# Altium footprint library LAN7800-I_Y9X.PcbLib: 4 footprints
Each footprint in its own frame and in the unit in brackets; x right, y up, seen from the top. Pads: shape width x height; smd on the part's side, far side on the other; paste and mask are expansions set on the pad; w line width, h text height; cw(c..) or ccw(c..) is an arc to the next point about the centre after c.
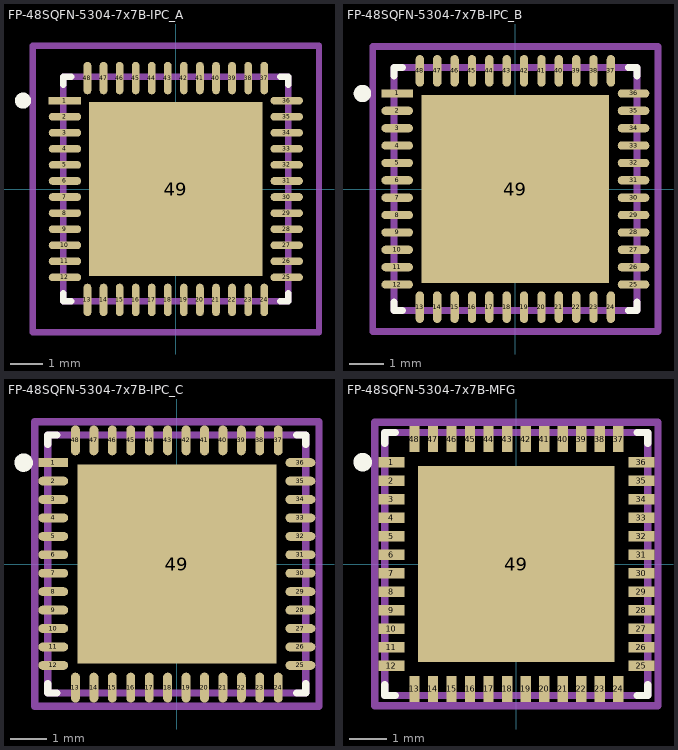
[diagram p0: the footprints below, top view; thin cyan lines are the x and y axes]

## FP-48SQFN-5304-7x7B-IPC_A [mm]
pads (49):
  rect 1.01x0.239 smd paste+0 mask+0: 1(-3.451,2.75)
  rrect100% 1.01x0.239 smd paste+0 mask+0: 2(-3.451,2.25) 3(-3.451,1.75) 4(-3.451,1.25) 5(-3.451,0.75) 6(-3.451,0.25) 7(-3.451,-0.25) 8(-3.451,-0.75) 9(-3.451,-1.25) 10(-3.451,-1.75) 11(-3.451,-2.25) 12(-3.451,-2.75) 25(3.451,-2.75) 26(3.451,-2.25) 27(3.451,-1.75) 28(3.451,-1.25) 29(3.451,-0.75) 30(3.451,-0.25) 31(3.451,0.25) 32(3.451,0.75) 33(3.451,1.25) 34(3.451,1.75) 35(3.451,2.25) 36(3.451,2.75)
  rrect100% 0.239x1.01 smd paste+0 mask+0: 13(-2.75,-3.451) 14(-2.25,-3.451) 15(-1.75,-3.451) 16(-1.25,-3.451) 17(-0.75,-3.451) 18(-0.25,-3.451) 19(0.25,-3.451) 20(0.75,-3.451) 21(1.25,-3.451) 22(1.75,-3.451) 23(2.25,-3.451) 24(2.75,-3.451) 37(2.75,3.451) 38(2.25,3.451) 39(1.75,3.451) 40(1.25,3.451) 41(0.75,3.451) 42(0.25,3.451) 43(-0.25,3.451) 44(-0.75,3.451) 45(-1.25,3.451) 46(-1.75,3.451) 47(-2.25,3.451) 48(-2.75,3.451)
  rect 5.4x5.4 smd paste-1000 mask+0: 49(0,0)
Top Overlay:
  circle w0.25: c-4.756,2.75 r0.125
  lines w0.2: -3.5,-3.25 -3.5,-3.5 -3.25,-3.5 ; -3.5,3.25 -3.5,3.5 -3.25,3.5 ; 3.25,-3.5 3.5,-3.5 3.5,-3.25 ; 3.25,3.5 3.5,3.5 3.5,3.25
Top Paste:
  rectangle: -2.038,0.331 -0.331,2.038
  rectangle: 0.331,0.331 2.038,2.038
  rectangle: -2.038,-2.038 -0.331,-0.331
  rectangle: 0.331,-2.038 2.038,-0.331
Top Assembly:
  lines w0.2: -4.456,-4.456 4.456,-4.456 4.456,4.456 -4.456,4.456 -4.456,-4.456
  text ".Designator" at 0,-0.001 h1
Top 3D Body:
  lines w0.2: -3.5,-3.5 3.5,-3.5 3.5,3.5 -3.5,3.5 -3.5,-3.5
Top Courtyard:
  lines w0.2: -4.456,-4.456 4.456,-4.456 4.456,4.456 -4.456,4.456 -4.456,-4.456
Top Component Center:
  lines w0.1: -0.5,0 0.5,0 ; 0,-0.5 0,0.5
3D body "IC_Microchip_LAN7800-I-Y9X_eec.STEP": height 0.25, standoff 0, extent -4.456,-4.456 4.456,4.456

## FP-48SQFN-5304-7x7B-IPC_B [mm]
pads (49):
  rect 0.91x0.239 smd paste+0 mask+0: 1(-3.401,2.75)
  rrect100% 0.91x0.239 smd paste+0 mask+0: 2(-3.401,2.25) 3(-3.401,1.75) 4(-3.401,1.25) 5(-3.401,0.75) 6(-3.401,0.25) 7(-3.401,-0.25) 8(-3.401,-0.75) 9(-3.401,-1.25) 10(-3.401,-1.75) 11(-3.401,-2.25) 12(-3.401,-2.75) 25(3.401,-2.75) 26(3.401,-2.25) 27(3.401,-1.75) 28(3.401,-1.25) 29(3.401,-0.75) 30(3.401,-0.25) 31(3.401,0.25) 32(3.401,0.75) 33(3.401,1.25) 34(3.401,1.75) 35(3.401,2.25) 36(3.401,2.75)
  rrect100% 0.239x0.91 smd paste+0 mask+0: 13(-2.75,-3.401) 14(-2.25,-3.401) 15(-1.75,-3.401) 16(-1.25,-3.401) 17(-0.75,-3.401) 18(-0.25,-3.401) 19(0.25,-3.401) 20(0.75,-3.401) 21(1.25,-3.401) 22(1.75,-3.401) 23(2.25,-3.401) 24(2.75,-3.401) 37(2.75,3.401) 38(2.25,3.401) 39(1.75,3.401) 40(1.25,3.401) 41(0.75,3.401) 42(0.25,3.401) 43(-0.25,3.401) 44(-0.75,3.401) 45(-1.25,3.401) 46(-1.75,3.401) 47(-2.25,3.401) 48(-2.75,3.401)
  rect 5.4x5.4 smd paste-1000 mask+0: 49(0,0)
Top Overlay:
  circle w0.25: c-4.406,2.75 r0.125
  lines w0.2: -3.5,-3.25 -3.5,-3.5 -3.25,-3.5 ; -3.5,3.25 -3.5,3.5 -3.25,3.5 ; 3.25,-3.5 3.5,-3.5 3.5,-3.25 ; 3.25,3.5 3.5,3.5 3.5,3.25
Top Paste:
  rectangle: -2.038,0.331 -0.331,2.038
  rectangle: 0.331,0.331 2.038,2.038
  rectangle: -2.038,-2.038 -0.331,-0.331
  rectangle: 0.331,-2.038 2.038,-0.331
Top Assembly:
  lines w0.2: -4.106,-4.106 4.106,-4.106 4.106,4.106 -4.106,4.106 -4.106,-4.106
  text ".Designator" at 0,-0.001 h1
Top 3D Body:
  lines w0.2: -3.5,-3.5 3.5,-3.5 3.5,3.5 -3.5,3.5 -3.5,-3.5
Top Courtyard:
  lines w0.2: -4.106,-4.106 4.106,-4.106 4.106,4.106 -4.106,4.106 -4.106,-4.106
Top Component Center:
  lines w0.1: -0.5,0 0.5,0 ; 0,-0.5 0,0.5
3D body "IC_Microchip_LAN7800-I-Y9X_eec.STEP": height 0.25, standoff 0, extent -4.106,-4.106 4.106,4.106

## FP-48SQFN-5304-7x7B-IPC_C [mm]
pads (49):
  rect 0.81x0.239 smd paste+0 mask+0: 1(-3.351,2.75)
  rrect100% 0.81x0.239 smd paste+0 mask+0: 2(-3.351,2.25) 3(-3.351,1.75) 4(-3.351,1.25) 5(-3.351,0.75) 6(-3.351,0.25) 7(-3.351,-0.25) 8(-3.351,-0.75) 9(-3.351,-1.25) 10(-3.351,-1.75) 11(-3.351,-2.25) 12(-3.351,-2.75) 25(3.351,-2.75) 26(3.351,-2.25) 27(3.351,-1.75) 28(3.351,-1.25) 29(3.351,-0.75) 30(3.351,-0.25) 31(3.351,0.25) 32(3.351,0.75) 33(3.351,1.25) 34(3.351,1.75) 35(3.351,2.25) 36(3.351,2.75)
  rrect100% 0.239x0.81 smd paste+0 mask+0: 13(-2.75,-3.351) 14(-2.25,-3.351) 15(-1.75,-3.351) 16(-1.25,-3.351) 17(-0.75,-3.351) 18(-0.25,-3.351) 19(0.25,-3.351) 20(0.75,-3.351) 21(1.25,-3.351) 22(1.75,-3.351) 23(2.25,-3.351) 24(2.75,-3.351) 37(2.75,3.351) 38(2.25,3.351) 39(1.75,3.351) 40(1.25,3.351) 41(0.75,3.351) 42(0.25,3.351) 43(-0.25,3.351) 44(-0.75,3.351) 45(-1.25,3.351) 46(-1.75,3.351) 47(-2.25,3.351) 48(-2.75,3.351)
  rect 5.4x5.4 smd paste-1000 mask+0: 49(0,0)
Top Overlay:
  circle w0.25: c-4.156,2.75 r0.125
  lines w0.2: -3.5,-3.25 -3.5,-3.5 -3.25,-3.5 ; -3.5,3.25 -3.5,3.5 -3.25,3.5 ; 3.25,-3.5 3.5,-3.5 3.5,-3.25 ; 3.25,3.5 3.5,3.5 3.5,3.25
Top Paste:
  rectangle: -2.038,0.331 -0.331,2.038
  rectangle: 0.331,0.331 2.038,2.038
  rectangle: -2.038,-2.038 -0.331,-0.331
  rectangle: 0.331,-2.038 2.038,-0.331
Top Assembly:
  lines w0.2: -3.856,-3.856 3.856,-3.856 3.856,3.856 -3.856,3.856 -3.856,-3.856
  text ".Designator" at 0,-0.001 h1
Top 3D Body:
  lines w0.2: -3.5,-3.5 3.5,-3.5 3.5,3.5 -3.5,3.5 -3.5,-3.5
Top Courtyard:
  lines w0.2: -3.856,-3.856 3.856,-3.856 3.856,3.856 -3.856,3.856 -3.856,-3.856
Top Component Center:
  lines w0.1: -0.5,0 0.5,0 ; 0,-0.5 0,0.5
3D body "IC_Microchip_LAN7800-I-Y9X_eec.STEP": height 0.25, standoff 0, extent -3.856,-3.856 3.856,3.856

## FP-48SQFN-5304-7x7B-MFG [mm]
pads (49):
  rect 0.7x0.28 smd paste+0 mask+0: 1(-3.375,2.75) 2(-3.375,2.25) 3(-3.375,1.75) 4(-3.375,1.25) 5(-3.375,0.75) 6(-3.375,0.25) 7(-3.375,-0.25) 8(-3.375,-0.75) 9(-3.375,-1.25) 10(-3.375,-1.75) 11(-3.375,-2.25) 12(-3.375,-2.75) 25(3.375,-2.75) 26(3.375,-2.25) 27(3.375,-1.75) 28(3.375,-1.25) 29(3.375,-0.75) 30(3.375,-0.25) 31(3.375,0.25) 32(3.375,0.75) 33(3.375,1.25) 34(3.375,1.75) 35(3.375,2.25) 36(3.375,2.75)
  rect 0.28x0.7 smd paste+0 mask+0: 13(-2.75,-3.375) 14(-2.25,-3.375) 15(-1.75,-3.375) 16(-1.25,-3.375) 17(-0.75,-3.375) 18(-0.25,-3.375) 19(0.25,-3.375) 20(0.75,-3.375) 21(1.25,-3.375) 22(1.75,-3.375) 23(2.25,-3.375) 24(2.75,-3.375) 37(2.75,3.375) 38(2.25,3.375) 39(1.75,3.375) 40(1.25,3.375) 41(0.75,3.375) 42(0.25,3.375) 43(-0.25,3.375) 44(-0.75,3.375) 45(-1.25,3.375) 46(-1.75,3.375) 47(-2.25,3.375) 48(-2.75,3.375)
  rect 5.3x5.3 smd paste+0 mask+0: 49(0,0)
Top Overlay:
  circle w0.25: c-4.15,2.75 r0.125
  lines w0.2: -3.55,-3.265 -3.55,-3.55 -3.265,-3.55 ; -3.55,3.265 -3.55,3.55 -3.265,3.55 ; 3.265,-3.55 3.55,-3.55 3.55,-3.265 ; 3.265,3.55 3.55,3.55 3.55,3.265
Top Assembly:
  lines w0.2: -3.825,-3.825 3.825,-3.825 3.825,3.825 -3.825,3.825 -3.825,-3.825
  text ".Designator" at 0,0.188 h1
Top 3D Body:
  lines w0.2: -3.55,-3.55 3.55,-3.55 3.55,3.55 -3.55,3.55 -3.55,-3.55
Top Courtyard:
  lines w0.2: -3.825,-3.825 3.825,-3.825 3.825,3.825 -3.825,3.825 -3.825,-3.825
Top Component Center:
  lines w0.1: -0.5,0 0.5,0 ; 0,-0.5 0,0.5
3D body "IC_Microchip_LAN7800-I-Y9X_eec.STEP": height 0.25, standoff 0, extent -3.825,-3.825 3.825,3.825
